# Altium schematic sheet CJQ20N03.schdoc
size 127 x 101 mm
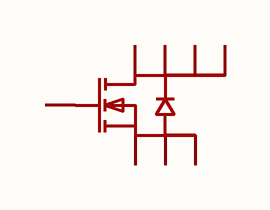
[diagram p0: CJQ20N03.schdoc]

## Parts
Q?  cjq20n03  [SOP-8_L4.9-W3.9-P1.27-LS6.0-BL]  (value not drawn)

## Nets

Not connected (* = marked no-connect by the designer): Q? 1(S) 2(S) 3(S) 4(G) 5(D) 6(D) 7(D) 8(D)

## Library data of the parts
Q? = cjq20n03: 数量:1个N沟道;漏源电压(Vdss):30V;连续漏极电流(Id):20A;导通电阻(RDS(on)):3.1mΩ@10V;耗散功率(Pd):1.4W;阈值电压(Vgs(th)):1V;; Manufacturer: CJ(江苏长电/长晶); AddInBom: yes; ModelId: 75c24a7891ee4dd6bdac16a7163ff87e; ModelName: SOP-8_L4.9-W3.9-P1.27-LS6.0-BL-1; ModelTransform: 192.913,236.22,0,0,0,0,-0.393,2.749,0; Number: 1个N沟道; Drain to Source Voltage: 30V; Current - Continuous Drain(Id): 20A; Pd - Power Dissipation: 1.4W; Gate Threshold Voltage (Vgs(th)): 1V; Gate Charge(Qg): 54nC@10V; Input Capacitance(Ciss): 2.412nF; Reverse Transfer Capacitance (Crss@Vds): 396pF; Type: N沟道; Output Capacitance(Coss): 420pF; Vgs: ±20V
